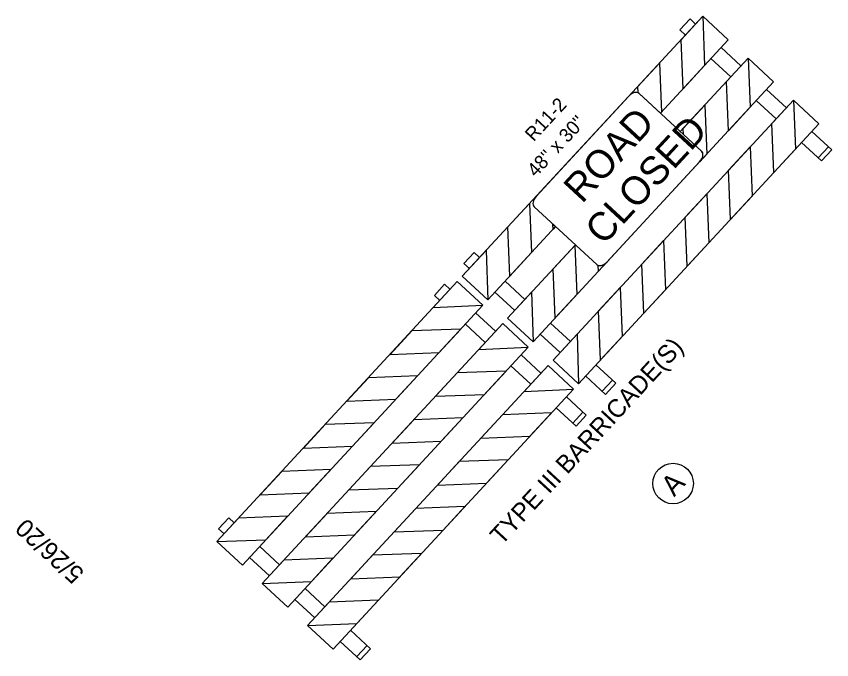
# Model space of a CAD drawing. Extents: x 1767460 to 1770129, y 996106 to 1001438.
# Drawn here: x 1767460 to 1769234, y 996106 to 997507 of the extents above; entities that cross this region are included whole.
import ezdxf

# ---------------------------------------------------------------- set-up
doc = ezdxf.new("R2010")
doc.units = 0
for name, color, linetype in [('P_NCDOT_Terrain_Points_Random', 7, 'Continuous'), ('P_NCDOT_Terrain_Triangle_Vertices', 7, 'Continuous'), ('P_RDY_Slope_Stake_Fill_Limits', 7, 'Continuous'), ('P_RDY_TC_Draft-DNC', 7, 'Continuous')]:
    doc.layers.add(name, color=color, linetype=linetype)

msp = doc.modelspace()

# ---------------------------------------------------------------- linework, layer by layer
at = {"layer": 'P_NCDOT_Terrain_Points_Random'}
msp.add_circle((1768889, 996489.7), 44.1, dxfattribs=at)
at = {"layer": 'P_NCDOT_Terrain_Triangle_Vertices'}
msp.add_circle((1768889, 996489.7), 44.1, dxfattribs=at)
at = {"layer": 'P_RDY_Slope_Stake_Fill_Limits'}
for p, q in [((1768430.4, 996940.8), (1768953.5, 997506.6)), ((1768906.4, 997455.7), (1768953.5, 997506.6)), ((1768953.5, 997506.6), (1769008.9, 997455.4)), ((1768953.5, 997506.6), (1768957.7, 997399.9)), ((1768925.9, 997500.9), (1768903.7, 997476.9)), ((1768925.9, 997500.9), (1768937.9, 997489.8)), ((1768903.7, 997476.9), (1768915.7, 997465.8)), ((1769008.9, 997455.4), (1768861.4, 997295.8)), ((1768910.6, 997349), (1768906.4, 997455.7)), ((1768993.4, 997438.5), (1769036.6, 997398.6)), ((1768812.2, 997353.9), (1768859.3, 997404.8)), ((1768859.3, 997404.8), (1768863.5, 997298)), ((1768904.7, 997255.8), (1769052.2, 997415.4)), ((1768957.7, 997399.9), (1768910.6, 997349)), ((1768971.2, 997414.5), (1769014.4, 997374.6)), ((1769005.1, 997364.5), (1769052.2, 997415.4)), ((1769052.2, 997415.4), (1769107.7, 997364.1)), ((1769052.2, 997415.4), (1769056.4, 997308.6)), ((1769107.7, 997364.1), (1768584.6, 996798.2)), ((1769009.3, 997257.7), (1769005.1, 997364.5)), ((1768812.8, 997340.2), (1768812.2, 997353.9)), ((1769092.1, 997347.3), (1769135.4, 997307.3)), ((1768861.4, 997295.8), (1768814.9, 997338.7)), ((1768627.8, 996758.3), (1769150.9, 997324.1)), ((1768911, 997262.6), (1768958, 997313.5)), ((1768958, 997313.5), (1768962.2, 997206.8)), ((1769069.9, 997323.3), (1769113.1, 997283.3)), ((1769103.8, 997273.2), (1769150.9, 997324.1)), ((1769150.9, 997324.1), (1769155.1, 997217.4)), ((1769150.9, 997324.1), (1769206.4, 997272.9)), ((1768863.5, 997298), (1768861.4, 997295.8)), ((1769056.4, 997308.6), (1769009.3, 997257.7)), ((1769206.4, 997272.9), (1768683.3, 996707)), ((1768911.5, 997249.5), (1768911, 997262.6)), ((1769108, 997166.4), (1769103.8, 997273.2)), ((1768951.1, 997212.8), (1768911.5, 997249.5)), ((1769190.8, 997256), (1769234.1, 997216.1)), ((1769009.7, 997171.4), (1769056.8, 997222.3)), ((1769056.8, 997222.3), (1769061, 997115.5)), ((1769168.6, 997232), (1769211.9, 997192.1)), ((1769226.9, 997222.7), (1769204.7, 997198.7)), ((1768962.2, 997206.8), (1768946.9, 997190.2)), ((1769155.1, 997217.4), (1769108, 997166.4)), ((1769234.1, 997216.1), (1769211.9, 997192.1)), ((1768946.8, 997190.1), (1768745.4, 996972.2)), ((1769013.9, 997064.6), (1769009.7, 997171.4)), ((1768915.5, 997069.5), (1768962.6, 997120.5)), ((1768962.6, 997120.5), (1768966.8, 997013.7)), ((1769061, 997115.5), (1769013.9, 997064.6)), ((1768529.6, 997048.1), (1768576.7, 997099)), ((1768576.7, 997099), (1768580.9, 996992.3)), ((1768919.7, 996962.8), (1768915.5, 997069.5)), ((1768633.4, 997049), (1768485.9, 996889.5)), ((1768533.8, 996941.3), (1768529.6, 997048.1)), ((1768628, 997043.2), (1768627.5, 997054.5)), ((1768627.5, 997054.5), (1768633.4, 997049)), ((1768633.4, 997049), (1768628, 997043.2)), ((1768529.1, 996849.5), (1768676.6, 997009.1)), ((1768821.2, 996967.5), (1768868.3, 997018.4)), ((1768868.3, 997018.4), (1768872.5, 996911.6)), ((1768966.8, 997013.7), (1768919.7, 996962.8)), ((1768430.4, 996940.8), (1768482.5, 996997.2)), ((1768456.1, 996992.7), (1768433.9, 996968.7)), ((1768456.1, 996992.7), (1768468.1, 996981.6)), ((1768482.5, 996997.2), (1768485.9, 996889.5)), ((1768580.9, 996992.3), (1768533.8, 996941.3)), ((1768628.3, 996956.9), (1768675.4, 997007.8)), ((1768675.4, 997007.8), (1768679.6, 996901)), ((1768433.9, 996968.7), (1768445.9, 996957.6)), ((1768632.5, 996850.1), (1768628.3, 996956.9)), ((1768726.7, 996951.9), (1768726.2, 996964.3)), ((1768745.4, 996972.2), (1768726.7, 996951.9)), ((1768825.4, 996860.7), (1768821.2, 996967.5)), ((1768485.9, 996889.5), (1768430.4, 996940.8)), ((1768485.9, 996889.5), (1768430.4, 996940.8)), ((1768419.6, 996929.1), (1767896.5, 996363.2)), ((1768419.6, 996929.1), (1768367.4, 996872.6)), ((1768369.8, 996899.3), (1768392, 996923.3)), ((1768392, 996923.3), (1768404, 996912.2)), ((1768475, 996877.8), (1768419.6, 996929.1)), ((1768475, 996877.8), (1768419.6, 996929.1)), ((1768523.6, 996930.3), (1768566.8, 996890.3)), ((1768501.4, 996906.3), (1768544.6, 996866.3)), ((1768529.1, 996849.5), (1768581.3, 996905.9)), ((1768581.3, 996905.9), (1768584.6, 996798.2)), ((1768727.1, 996865.6), (1768774.1, 996916.5)), ((1768774.1, 996916.5), (1768778.3, 996809.8)), ((1768872.5, 996911.6), (1768825.4, 996860.7)), ((1768369.8, 996899.3), (1768381.8, 996888.2)), ((1768679.6, 996901), (1768632.5, 996850.1)), ((1767952, 996311.9), (1768475, 996877.8)), ((1768367.4, 996872.6), (1768475, 996877.8)), ((1768459.5, 996861), (1768502.7, 996821)), ((1768584.6, 996798.2), (1768529.1, 996849.5)), ((1768584.6, 996798.2), (1768529.1, 996849.5)), ((1768731.3, 996758.8), (1768727.1, 996865.6)), ((1768518.3, 996837.8), (1767995.2, 996271.9)), ((1768437.3, 996836.9), (1768480.5, 996797)), ((1768518.3, 996837.8), (1768466.1, 996781.4)), ((1768573.8, 996786.5), (1768518.3, 996837.8)), ((1768573.8, 996786.5), (1768518.3, 996837.8)), ((1768622.3, 996839), (1768665.6, 996799.1)), ((1768320.3, 996821.7), (1768273.2, 996770.8)), ((1768427.1, 996825.9), (1768320.3, 996821.7)), ((1768380, 996775), (1768427.1, 996825.9)), ((1768600.1, 996815), (1768643.4, 996775.1)), ((1768627.8, 996758.3), (1768680, 996814.7)), ((1768680, 996814.7), (1768683.3, 996707)), ((1768778.3, 996809.8), (1768731.3, 996758.8)), ((1768050.7, 996220.6), (1768573.8, 996786.5)), ((1768466.1, 996781.4), (1768573.8, 996786.5)), ((1768273.2, 996770.8), (1768380, 996775)), ((1768558.2, 996769.7), (1768601.5, 996729.7)), ((1768617, 996746.6), (1768093.9, 996180.7)), ((1768536, 996745.7), (1768579.3, 996705.7)), ((1768617, 996746.6), (1768564.8, 996690.1)), ((1768672.5, 996695.3), (1768617, 996746.6)), ((1768672.5, 996695.3), (1768617, 996746.6)), ((1768683.3, 996707), (1768627.8, 996758.3)), ((1768683.3, 996707), (1768627.8, 996758.3)), ((1768721, 996747.8), (1768764.3, 996707.8)), ((1768419, 996730.4), (1768372, 996679.5)), ((1768525.8, 996734.6), (1768419, 996730.4)), ((1768478.7, 996683.7), (1768525.8, 996734.6)), ((1768226.2, 996719.8), (1768179.1, 996668.9)), ((1768333, 996724), (1768226.2, 996719.8)), ((1768285.9, 996673.1), (1768333, 996724)), ((1768698.8, 996723.8), (1768742.1, 996683.8)), ((1768757.1, 996714.5), (1768734.9, 996690.5)), ((1768764.3, 996707.8), (1768742.1, 996683.8)), ((1768149.4, 996129.4), (1768672.5, 996695.3)), ((1768564.8, 996690.1), (1768672.5, 996695.3)), ((1768179.1, 996668.9), (1768285.9, 996673.1)), ((1768372, 996679.5), (1768478.7, 996683.7)), ((1768656.9, 996678.5), (1768700.2, 996638.5)), ((1768634.7, 996654.4), (1768678, 996614.5)), ((1768517.8, 996639.2), (1768470.7, 996588.3)), ((1768624.5, 996643.4), (1768517.8, 996639.2)), ((1768577.5, 996592.5), (1768624.5, 996643.4)), ((1768670.8, 996621.1), (1768693, 996645.1)), ((1768678, 996614.5), (1768700.2, 996638.5)), ((1768238.6, 996622), (1768131.8, 996617.8)), ((1768191.5, 996571), (1768238.6, 996622)), ((1768324.9, 996628.6), (1768277.8, 996577.7)), ((1768431.7, 996632.8), (1768324.9, 996628.6)), ((1768384.6, 996581.9), (1768431.7, 996632.8)), ((1768131.8, 996617.8), (1768084.8, 996566.8)), ((1768470.7, 996588.3), (1768577.5, 996592.5)), ((1768084.8, 996566.8), (1768191.5, 996571)), ((1768277.8, 996577.7), (1768384.6, 996581.9)), ((1768337.3, 996530.7), (1768230.5, 996526.5)), ((1768290.2, 996479.8), (1768337.3, 996530.7)), ((1768423.6, 996537.3), (1768376.5, 996486.4)), ((1768530.4, 996541.5), (1768423.6, 996537.3)), ((1768483.3, 996490.6), (1768530.4, 996541.5)), ((1768037.7, 996515.9), (1767990.6, 996465)), ((1768144.5, 996520.1), (1768037.7, 996515.9)), ((1768097.4, 996469.2), (1768144.5, 996520.1)), ((1768230.5, 996526.5), (1768183.5, 996475.6)), ((1768183.5, 996475.6), (1768290.2, 996479.8)), ((1768376.5, 996486.4), (1768483.3, 996490.6)), ((1767990.6, 996465), (1768097.4, 996469.2)), ((1768136.4, 996424.7), (1768089.3, 996373.8)), ((1768243.2, 996428.9), (1768136.4, 996424.7)), ((1768196.1, 996378), (1768243.2, 996428.9)), ((1768329.3, 996435.3), (1768282.2, 996384.3)), ((1768436, 996439.5), (1768329.3, 996435.3)), ((1768389, 996388.5), (1768436, 996439.5)), ((1767943.5, 996414.1), (1767896.5, 996363.2)), ((1767900, 996391.1), (1767922.2, 996415.1)), ((1767922.2, 996415.1), (1767934.2, 996404)), ((1768050.3, 996418.3), (1767943.5, 996414.1)), ((1768003.3, 996367.4), (1768050.3, 996418.3)), ((1767900, 996391.1), (1767912, 996380)), ((1768282.2, 996384.3), (1768389, 996388.5)), ((1768089.3, 996373.8), (1768196.1, 996378)), ((1767896.5, 996363.2), (1768003.3, 996367.4)), ((1767896.5, 996363.2), (1767952, 996311.9)), ((1767989.7, 996352.7), (1768032.9, 996312.7)), ((1768341.9, 996337.6), (1768235.1, 996333.4)), ((1768294.8, 996286.7), (1768341.9, 996337.6)), ((1767967.5, 996328.7), (1768010.7, 996288.7)), ((1768042.3, 996322.8), (1767995.2, 996271.9)), ((1768149, 996327), (1768042.3, 996322.8)), ((1768102, 996276.1), (1768149, 996327)), ((1768235.1, 996333.4), (1768188.1, 996282.5)), ((1768188.1, 996282.5), (1768294.8, 996286.7)), ((1767995.2, 996271.9), (1768102, 996276.1)), ((1767995.2, 996271.9), (1768050.7, 996220.6)), ((1768088.4, 996261.5), (1768131.7, 996221.5)), ((1768066.2, 996237.4), (1768109.5, 996197.5)), ((1768141, 996231.6), (1768093.9, 996180.7)), ((1768247.8, 996235.8), (1768141, 996231.6)), ((1768200.7, 996184.9), (1768247.8, 996235.8)), ((1768093.9, 996180.7), (1768200.7, 996184.9)), ((1768093.9, 996180.7), (1768149.4, 996129.4)), ((1768187.1, 996170.2), (1768230.4, 996130.2)), ((1768164.9, 996146.2), (1768208.2, 996106.2)), ((1768201, 996112.9), (1768223.2, 996136.9)), ((1768208.2, 996106.2), (1768230.4, 996130.2))]:
    msp.add_line(p, q, dxfattribs=at)
for points in [[(1768591.2, 997114.7), (1768792.6, 997332.7)], [(1768814.9, 997338.7), (1768951.1, 997212.8)], [(1768723.1, 996966.1), (1768586.9, 997092)]]:
    msp.add_lwpolyline(points, dxfattribs=at)
for centre, major_axis, start_param, end_param in [((1768801.6, 997324.4), (13.3, 14.4), 0, 1.570796), ((1768801.6, 997324.4), (13.3, 14.4), 6.283185, 6.491582), ((1768937.8, 997198.4), (-13.3, -14.4), 1.570796, 3.141593), ((1768937.8, 997198.4), (13.3, 14.4), 4.712389, 6.283185), ((1768600.2, 997106.4), (-13.3, -14.4), 4.712162, 6.283185), ((1768736.4, 996980.5), (-13.3, -14.4), 0, 1.571024), ((1768736.4, 996980.5), (-13.3, -14.4), 0.287132, 1.570688)]:
    msp.add_ellipse(centre, major_axis=major_axis, ratio=0.625, start_param=start_param, end_param=end_param, dxfattribs=at)

# ---------------------------------------------------------------- texts
at = {"layer": 'P_NCDOT_Terrain_Points_Random'}
msp.add_text('A', height=44.3, rotation=47.2512, dxfattribs=at).set_placement((1768891.2, 996459.5))
at = {"layer": 'P_RDY_Slope_Stake_Fill_Limits'}
for s, height, p in [('R11-2', 29.88, (1768585.7, 997232.4)), ('ROAD', 61.6, (1768690.8, 997097.3)), ("48'' x 30''", 29.88, (1768590.4, 997154.9)), ('CLOSED', 61.6, (1768737.5, 997006.2)), ('TYPE III BARRICADE(S)', 39.25, (1768516.1, 996353.9))]:
    msp.add_text(s, height=height, rotation=47.2512, dxfattribs=at).set_placement(p)
at = {"layer": 'P_RDY_TC_Draft-DNC'}
msp.add_text('5/26/20', height=39.38, rotation=137.2512, dxfattribs=at).set_placement((1767610.3, 996297.2))

doc.saveas('drawing.dxf')
